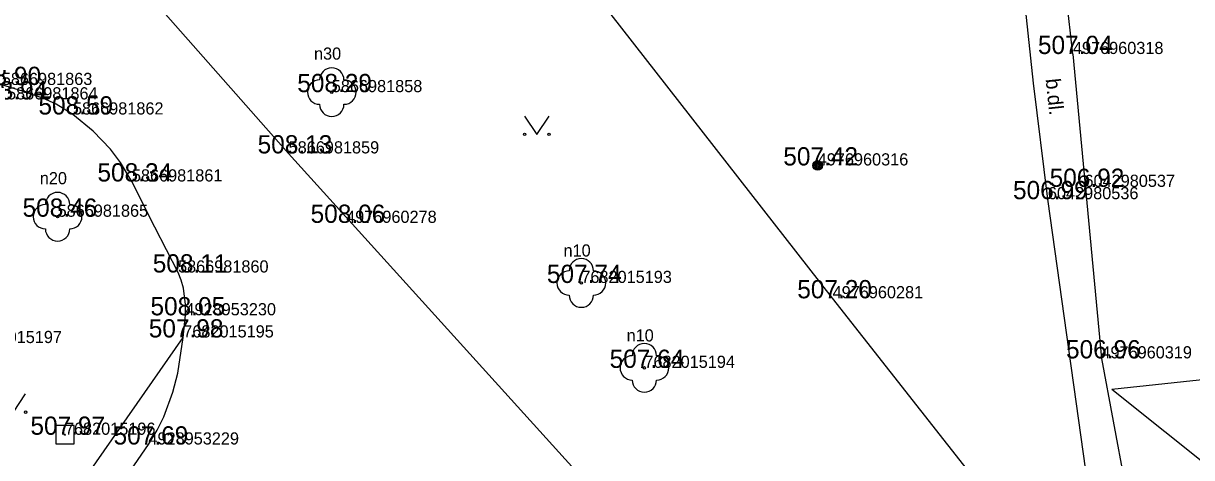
# Model space of a CAD drawing. Extents: x -669251 to -668549, y -1128351 to -1127698.
# Drawn here: x -668695.76 to -668647.77, y -1127970.02 to -1127952.17 of the extents above; entities that cross this region are included whole.
import ezdxf

# ---------------------------------------------------------------- set-up
doc = ezdxf.new("R2010")
doc.units = 0
for name, color, linetype in [('Vrstva 1', 7, 'Continuous'), ('Vrstva 10', 7, 'Continuous'), ('Vrstva 14', 7, 'Continuous'), ('Vrstva 2', 7, 'Continuous'), ('Vrstva 22', 7, 'Continuous'), ('Vrstva 25', 7, 'Continuous'), ('Vrstva 26', 7, 'Continuous'), ('Vrstva 3', 7, 'Continuous'), ('Vrstva 36', 7, 'Continuous'), ('Vrstva 40', 7, 'Continuous'), ('Vrstva 47', 7, 'Continuous'), ('Vrstva 7', 7, 'Continuous'), ('Vrstva 9', 7, 'Continuous')]:
    doc.layers.add(name, color=color, linetype=linetype)

msp = doc.modelspace()

# ---------------------------------------------------------------- linework, layer by layer
at = {"layer": 'Vrstva 1'}
for p, q in [((-668652.65, -1127953.43), (-668652.65, -1127953.43)), ((-668683.09, -1127954.998), (-668683.09, -1127954.998)), ((-668693.72, -1127955.916), (-668693.72, -1127955.916)), ((-668684.862, -1127957.516), (-668684.862, -1127957.516)), ((-668663.13, -1127958.01), (-668663.13, -1127958.01)), ((-668691.3, -1127958.669), (-668691.3, -1127958.669)), ((-668652.175, -1127958.891), (-668652.175, -1127958.891)), ((-668653.677, -1127959.397), (-668653.677, -1127959.397)), ((-668694.352, -1127960.118), (-668694.352, -1127960.118)), ((-668682.5, -1127960.37), (-668682.5, -1127960.37)), ((-668689.406, -1127962.41), (-668689.406, -1127962.41)), ((-668672.84, -1127962.84), (-668672.84, -1127962.84)), ((-668662.52, -1127963.47), (-668662.52, -1127963.47)), ((-668689.1, -1127964.17), (-668689.1, -1127964.17)), ((-668689.19, -1127965.08), (-668689.19, -1127965.08)), ((-668651.48, -1127965.94), (-668651.48, -1127965.94)), ((-668670.25, -1127966.33), (-668670.25, -1127966.33)), ((-668694.05, -1127969.08), (-668694.05, -1127969.08)), ((-668690.62, -1127969.48), (-668690.62, -1127969.48))]:
    msp.add_line(p, q, dxfattribs=at)
at = {"layer": 'Vrstva 10'}
msp.add_line((-668684.862, -1127957.516), (-668662.23, -1127982.55), dxfattribs=at)
for points in [[(-668690.243, -1127937.994), (-668691.685, -1127940.456), (-668693.127, -1127942.918), (-668693.337, -1127943.347), (-668693.473, -1127943.749), (-668693.607, -1127944.49), (-668693.627, -1127945.063), (-668693.538, -1127945.916), (-668693.32, -1127946.72), (-668692.967, -1127947.601), (-668692.659, -1127948.249), (-668692.116, -1127949.179), (-668691.468, -1127950.029), (-668688.165, -1127953.772), (-668684.862, -1127957.516)], [(-668651.54, -1127974.653), (-668652.608, -1127967.025), (-668653.677, -1127959.397), (-668654.269, -1127954.633), (-668654.779, -1127949.86), (-668654.919, -1127948.2), (-668654.898, -1127947.373), (-668654.756, -1127946.565), (-668654.496, -1127945.616), (-668654.236, -1127944.668)], [(-668691.3, -1127958.669), (-668691.764, -1127957.887), (-668692.175, -1127957.344), (-668692.891, -1127956.595), (-668693.72, -1127955.916), (-668694.414, -1127955.488), (-668694.954, -1127955.243), (-668695.788, -1127954.952), (-668696.643, -1127954.703), (-668697.63, -1127954.39), (-668698.395, -1127954.167), (-668698.965, -1127954.053), (-668699.383, -1127954.018), (-668699.984, -1127954.075), (-668700.268, -1127954.165), (-668700.539, -1127954.302), (-668700.748, -1127954.432), (-668700.958, -1127954.561)], [(-668690.353, -1127960.54), (-668691.3, -1127958.669)], [(-668689.406, -1127962.41), (-668690.353, -1127960.54)], [(-668692.655, -1127972.464), (-668691.638, -1127970.972), (-668690.62, -1127969.48), (-668690.261, -1127968.889), (-668689.992, -1127968.341), (-668689.619, -1127967.332), (-668689.412, -1127966.547), (-668689.19, -1127965.08), (-668689.1, -1127964.17), (-668689.098, -1127963.725), (-668689.183, -1127963.047), (-668689.275, -1127962.72), (-668689.406, -1127962.41)]]:
    msp.add_lwpolyline(points, dxfattribs=at)
at = {"layer": 'Vrstva 14'}
for p, q in [((-668704.23, -1127986.63), (-668689.19, -1127965.08)), ((-668645.1, -1127966.57), (-668651.053, -1127967.224)), ((-668636.138, -1127979.152), (-668651.053, -1127967.224))]:
    msp.add_line(p, q, dxfattribs=at)
at = {"layer": 'Vrstva 22'}
for centre in [(-668683.09, -1127954.998), (-668694.352, -1127960.118), (-668672.84, -1127962.84), (-668670.25, -1127966.33)]:
    msp.add_circle(centre, 0.05, dxfattribs=at)
for centre, start, end in [((-668683.09, -1127954.498), 0, 180), ((-668683.59, -1127954.998), 90, 270), ((-668682.59, -1127954.998), 270, 90), ((-668683.09, -1127955.498), 180, 0), ((-668694.352, -1127959.618), 0, 180), ((-668694.852, -1127960.118), 90, 270), ((-668693.852, -1127960.118), 270, 90), ((-668694.352, -1127960.618), 180, 0), ((-668672.84, -1127962.34), 0, 180), ((-668673.34, -1127962.84), 90, 270), ((-668672.34, -1127962.84), 270, 90), ((-668672.84, -1127963.34), 180, 0), ((-668670.25, -1127965.83), 0, 180), ((-668670.75, -1127966.33), 90, 270), ((-668669.75, -1127966.33), 270, 90), ((-668670.25, -1127966.83), 180, 0)]:
    msp.add_arc(centre, 0.5, start, end, dxfattribs=at)
at = {"layer": 'Vrstva 25'}
for radius in [0.2, 0.16, 0.12, 0.08, 0.04]:
    msp.add_circle((-668663.13, -1127958.01), radius, dxfattribs=at)
at = {"layer": 'Vrstva 26'}
msp.add_lwpolyline([(-668694.425, -1127969.455), (-668693.675, -1127969.455), (-668693.675, -1127968.705), (-668694.425, -1127968.705)], close=True, dxfattribs=at)
msp.add_circle((-668694.05, -1127969.08), 0.02, dxfattribs=at)
at = {"layer": 'Vrstva 36'}
for p, q in [((-668675.168, -1127955.984), (-668674.668, -1127956.734)), ((-668674.668, -1127956.734), (-668674.168, -1127955.984)), ((-668696.164, -1127968.15), (-668695.664, -1127967.4))]:
    msp.add_line(p, q, dxfattribs=at)
for centre in [(-668675.168, -1127956.734), (-668674.168, -1127956.734), (-668695.664, -1127968.15)]:
    msp.add_circle(centre, 0.05, dxfattribs=at)
at = {"layer": 'Vrstva 7'}
for p, q in [((-668662.52, -1127963.47), (-668675.617, -1127946.651)), ((-668652.96, -1127975.63), (-668662.52, -1127963.47))]:
    msp.add_line(p, q, dxfattribs=at)
at = {"layer": 'Vrstva 9'}
for p, q in [((-668652.65, -1127953.43), (-668653.055, -1127949.788)), ((-668652.65, -1127953.43), (-668651.48, -1127965.94)), ((-668651.48, -1127965.94), (-668649.84, -1127974.7))]:
    msp.add_line(p, q, dxfattribs=at)

# ---------------------------------------------------------------- texts
at = {"layer": 'Vrstva 2'}
for s, p in [('4976960318', (-668652.65, -1127953.43)), ('5866981863', (-668696.643, -1127954.703)), ('5866981858', (-668683.09, -1127954.998)), ('5866981864', (-668696.427, -1127955.296)), ('5866981862', (-668693.72, -1127955.916)), ('5866981859', (-668684.862, -1127957.516)), ('4976960316', (-668663.13, -1127958.01)), ('5866981861', (-668691.3, -1127958.669)), ('6042980537', (-668652.175, -1127958.891)), ('6042980536', (-668653.677, -1127959.397)), ('5866981865', (-668694.352, -1127960.118)), ('4976960278', (-668682.5, -1127960.37)), ('5866981860', (-668689.406, -1127962.41)), ('7682015193', (-668672.84, -1127962.84)), ('4976960281', (-668662.52, -1127963.47)), ('4928953230', (-668689.1, -1127964.17)), ('7682015195', (-668689.19, -1127965.08)), ('7682015197', (-668697.89, -1127965.31)), ('4976960319', (-668651.48, -1127965.94)), ('7682015194', (-668670.25, -1127966.33)), ('7682015196', (-668694.05, -1127969.08)), ('4928953229', (-668690.62, -1127969.48))]:
    msp.add_text(s, height=0.5, dxfattribs=at).set_placement(p)
at = {"layer": 'Vrstva 3'}
for s, p in [('507.04 ', (-668654.086, -1127953.43)), ('508.90 ', (-668698.096, -1127954.703)), ('508.94 ', (-668697.844, -1127955.296)), ('508.29 ', (-668684.508, -1127954.998)), ('508.59 ', (-668695.138, -1127955.916)), ('508.13 ', (-668686.136, -1127957.516)), ('507.42 ', (-668664.545, -1127958.01)), ('508.34 ', (-668692.715, -1127958.669)), ('506.92 ', (-668653.606, -1127958.891)), ('506.99 ', (-668655.111, -1127959.397)), ('508.46 ', (-668695.79, -1127960.118)), ('508.06 ', (-668683.96, -1127960.37)), ('508.11 ', (-668690.443, -1127962.41)), ('507.74 ', (-668674.255, -1127962.84)), ('507.20 ', (-668663.971, -1127963.47)), ('508.05 ', (-668690.536, -1127964.17)), ('507.98 ', (-668690.607, -1127965.08)), ('507.64 ', (-668671.679, -1127966.33)), ('506.96 ', (-668652.934, -1127965.94)), ('507.97 ', (-668695.467, -1127969.08)), ('507.69 ', (-668692.052, -1127969.48))]:
    msp.add_text(s, height=0.75, dxfattribs=at).set_placement(p)
at = {"layer": 'Vrstva 40'}
msp.add_text('b.dl.', height=0.6, rotation=275.9835, dxfattribs=at).set_placement((-668653.771, -1127954.465))
at = {"layer": 'Vrstva 47'}
for s, p in [('n30', (-668683.819, -1127953.662)), ('n20', (-668695.081, -1127958.782)), ('n10', (-668673.57, -1127961.754)), ('n10', (-668670.98, -1127965.244))]:
    msp.add_text(s, height=0.499, dxfattribs=at).set_placement(p)

doc.saveas('drawing.dxf')
